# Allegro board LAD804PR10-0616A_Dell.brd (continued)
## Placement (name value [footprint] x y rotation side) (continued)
RC954  10K_0402_5%  [R_0402]  133.93 47.01 0 top
RC967  0_0402_5%  [R_0402]  185.81 24.72 0 bottom
RC1672  0_0603_5%  [R_0603]  122.89 15 180 bottom
RC1675  0_0603_1%  [R0603_0OHM]  122.89 16.27 180 bottom
RD15  0_0402_5%  [R_0402]  175.35 41.51 270 bottom
RD23  1K_0402_1%  [R_0402]  62.45 58.44 180 top
RD24  1K_0402_1%  [R_0402]  61.54 44.91 0 top
RD25  0_0402_5%  [R0402_0OHM]  72.3 50.37 180 top
RD26  1K_0402_1%  [R_0402]  62.45 39.9 180 top
RD27  1K_0402_1%  [R_0402]  44.52 58.95 0 top
RD28  0_0402_5%  [R0402_0OHM]  52.41 51.38 90 top
RD29  0_0402_5%  [R0402_0OHM]  44.52 43.71 0 top
RD32  1K_0402_1%  [R_0402]  44.53 45.66 90 top
RD33  1K_0402_1%  [R_0402]  41.85 41.67 0 top
RE4  0_0805_5%  [R_0805]  176.02 31.85 0 top
RE5  0_0805_5%  [R0805_0OHM]  178.07 23.98 270 top
RE13  0_0805_5%  [R_0805]  176.02 33.63 0 top
RE14  0_0402_5%  [R_0402]  174.39 41.62 270 bottom
RE16  33_0402_5%  [R_0402]  183.97 32.85 0 bottom
RE19  1K_0402_1%  [R_0402]  187.17 30.24 180 bottom
RE20  100K_0402_1%  [R_0402]  166.9 20.54 270 bottom
RE21  10K_0402_5%  [R_0402]  186.72 25.67 180 bottom
RE22  270K_0402_1%  [R_0402]  165.88 19.63 90 bottom
RE23  100K_0402_1%  [R_0402]  164.1 40.71 90 bottom
RE24  0_0402_1%  [R_0402]  165.12 41.62 270 bottom
RE31  0_0402_5%  [R0402_0OHM]  162.88 27.96 0 bottom
RE32  0_0402_5%  [R0402_0OHM]  162.88 28.97 0 bottom
RE33  0_0402_5%  [R0402_0OHM]  162.88 29.99 0 bottom
RE34  0_0402_5%  [R0402_0OHM]  162.88 31.01 0 bottom
RE37  0_0402_5%  [R0402_0OHM]  184.88 34.82 180 bottom
RE38  0_0402_5%  [R0402_0OHM]  184.88 31.26 180 bottom
RE39  0_0402_5%  [R0402_0OHM]  171.02 41.61 270 bottom
RE40  0_0402_5%  [R_0402]  184.88 30.24 180 bottom
RE41  0_0402_5%  [R_0402]  184.88 25.67 180 bottom
RE42  0_0402_5%  [R0402_0OHM]  170.13 40.7 90 bottom
RE43  0_0402_5%  [R_0402]  176.37 40.59 90 bottom
RE44  0_0402_5%  [R_0402]  169.18 41.62 270 bottom
RE46  4.7K_0402_5%  [R_0402]  179.66 40.65 90 bottom
RE48  4.7K_0402_5%  [R_0402]  167.15 40.71 90 bottom
RE49  100K_0402_5%  [R_0402]  160.85 95.78 0 top
RE50  0_0402_5%  [R0402_0OHM]  177.88 38.96 270 top
RE51  0_0402_5%  [R0402_0OHM]  162.88 26.94 0 bottom
RE58  100K_0402_5%  [R_0402]  114.52 9.67 180 top
RE59  0_0805_5%  [R_0805]  120.19 13.67 180 bottom
RE60  240_0402_1%  [R_0402]  63.66 9.4 0 top
RE61  10K_0402_5%  [R_0402]  184.88 29.23 180 bottom
RE62  47K_0402_5%  [R_0402]  177.57 19.63 90 bottom
RE63  47K_0402_5%  [R_0402]  176.55 19.63 90 bottom
RE66  10K_0402_5%  [R_0402]  184.88 28.21 180 bottom
RE68  10K_0402_5%  [R_0402]  117.37 8.6 270 top
RE69  0_0402_5%  [R_0402]  176.87 38.96 270 top
RE70  10K_0402_5%  [R_0402]  162.88 34.56 0 bottom
RE75  10K_0402_5%  [R_0402]  174.77 35.12 90 top
RE338  0_0402_5%  [R0402_0OHM]  94.51 4.64 90 top
RE504  10K_0402_5%  [R_0402]  163.8 32.02 180 bottom
RE505  10K_0402_5%  [R_0402]  145.82 14.04 90 bottom
RF1  10K_0402_5%  [R_0402]  182.4 54.76 224.6 top
RF2  10K_0402_5%  [R_0402]  182.85 47.96 179.9 bottom
RF3  10K_0402_5%  [R_0402]  182.85 47.07 180 bottom
RH21  33_0402_5%  [R_0402]  94.95 74.77 270 top
RH22  10K_0402_5%  [R_0402]  94.65 76.85 180 top
RH23  10K_0402_5%  [R_0402]  94.65 77.74 180 top
RH24  10K_0402_5%  [R_0402]  94 79.79 270 top
RH25  33_0402_5%  [R_0402]  84.3 78.5 180 top
RI1  0_0402_5%  [R_0402-NPM]  20.04 85.72 180 top
RI2  0_0402_5%  [R_0402-NPM]  20.04 84.7 180 top
RI3  150_0402_5%  [R_0402]  17.55 85.67 270 top
RI4  0_0402_5%  [R_0402-NPM]  18.89 88.35 180 top
RI5  0_0402_5%  [R_0402-NPM]  18.89 87.33 180 top
RI6  150_0402_5%  [R_0402]  16.53 88.23 270 top
RI7  0_0402_5%  [R_0402-NPM]  18.96 82.72 180 top
RI8  0_0402_5%  [R_0402-NPM]  18.96 81.7 180 top
RI9  150_0402_5%  [R_0402]  16.53 82.72 270 top
RI10  0_0402_5%  [R_0402-NPM]  19.91 79.01 180 top
RI11  0_0402_5%  [R_0402-NPM]  19.91 80.03 180 top
RI12  150_0402_5%  [R_0402]  17.55 79.06 90 top
RI16  20K_0402_5%  [R_0402]  31.72 92.47 180 top
RI17  100K_0402_5%  [R_0402]  30.8 93.49 0 top
RI18  150K_0402_5%  [R_0402]  30.8 90.44 0 top
RI19  10K_0402_5%  [R_0402]  23.72 97.05 180 top
RI20  100K_0402_5%  [R_0402]  30.8 95.01 0 top
RL1  10K_0402_5%  [R_0402]  38.84 121.23 180 bottom
RL2  2.49K_0402_1%~D  [R_0402]  37.88 116.16 180 bottom
RL3  1K_0402_5%  [R_0402]  34.78 122.65 270 bottom
RL4  15K_0402_1%  [R_0402]  35.8 121.74 90 bottom
RL5  0_0603_1%  [R0603_0OHM]  39.83 113.3 180 bottom
RL6  100K_0402_5%  [R_0402]  22.17 121.94 0 bottom
RL7  10K_0402_5%  [R_0402]  22.17 120.92 0 bottom
RL8  0_0402_5%  [R_0402]  33.33 122.67 270 bottom
RL9  0_0402_5%  [R0402_0OHM]  32.31 121.75 90 bottom
RL10  10K_0402_5%  [R_0402]  36.82 122.65 270 bottom
RL11  10K_0402_5%  [R_0402]  29.18 117.62 180 bottom
RL12  10K_0402_5%  [R_0402]  23.08 122.95 180 bottom
RL14  75_0603_5%  [R_0603]  18.88 112.03 0 top
RL15  75_0603_5%  [R_0603]  18.88 108.48 0 top
RM7  0_1206_5%  [R_1206]  47.01 103.59 90 top
RP1  100K_0402_5%  [R_0402]  221.71 45.99 180 bottom
RP2  10K_0402_5%  [R_0402]  221.71 36.85 180 bottom
RP3  100K_0402_5%  [R_0402]  221.71 37.86 180 bottom
RP20  2.2K_0804_8P4R_5%  [RP_0804_8P4R]  105.31 24.77 180 bottom
RPC13  33_0804_8P4R_5%  [RP_0804_8P4R]  99.51 20.04 0 bottom
RPC14  1K_0804_8P4R_5%  [RP_0804_8P4R]  103.96 21.54 180 bottom
RPC25  1K_0804_8P4R_5%  [RP_0804_8P4R]  109.99 76.66 90 bottom
RPC30  1K_0804_8P4R_5%  [RP_0804_8P4R]  113.57 70.76 270 bottom
RPC36  10K_8P4R_5%  [RP_0804_8P4R]  140.8 41.18 180 top
RPC45  100K_0804_8P4R_5%  [RP_0804_8P4R]  114.31 88.22 270 top
RPC64  2.2K_0804_8P4R_5%  [RP_0804_8P4R]  100.67 38.49 180 bottom
RPE1  2.2K_0804_8P4R_5%  [RP_0804_8P4R]  166.97 28.99 180 top
RPH1  1K_0804_8P4R_5%  [RP_0804_8P4R]  83.91 70.64 180 top
RPH2  1K_0804_8P4R_5%  [RP_0804_8P4R]  83.91 79.79 180 top
RPI1  499_0804_8P4R_1%  [RP_0804_8P4R]  16.23 86.92 180 bottom
RPI2  499_0804_8P4R_1%  [RP_0804_8P4R]  16.23 80.74 180 bottom
RPI3  2.2K_0804_8P4R_5%  [RP_0804_8P4R]  22.56 95.64 0 top
RPV34  10K_8P4R_5%  [RP_0804_8P4R]  117.36 93.93 90 bottom
RS8  0_0402_5%  [R_0402]  194.38 18.56 0 bottom
RS18  0_0402_5%  [R_0402]  191.23 23.13 180 bottom
RS19  0_0402_5%  [R_0402]  200.63 28.72 180 bottom
RS20  0_0402_5%  [R_0402]  190.32 25.16 0 bottom
RS21  0_0402_5%  [R_0402]  199.71 26.69 0 bottom
RS22  0_0402_5%  [R_0402]  190.32 26.18 0 bottom
RS23  0_0402_5%  [R_0402]  191.23 27.2 180 bottom
RS24  2K_0402_5%  [R_0402]  199.71 25.67 0 bottom
RS25  0_0402_5%  [R_0402]  200.63 23.64 180 bottom
RS26  0_0402_5%  [R_0402]  190.32 29.23 0 bottom
RS27  0_0402_5%  [R_0402]  200.63 24.66 180 bottom
RS28  0_0402_5%  [R_0402]  200.63 27.7 180 bottom
RS29  0_0402_5%  [R_0402]  190.32 24.15 0 bottom
RS30  0_0402_5%  [R_0402]  190.32 28.21 0 bottom
RS31  5.1K_0402_1%  [R_0402]  191.23 30.24 180 bottom
RS33  4.7K_0402_5%  [R_0402]  199.71 29.74 0 bottom
RS34  4.7K_0402_5%  [R_0402]  191.23 21.1 180 bottom
RS35  4.7K_0402_5%  [R_0402]  199.71 30.75 0 bottom
RS36  4.7K_0402_5%  [R_0402]  191.23 22.12 180 bottom
RS37  0_0402_5%  [R_0402]  196.25 24.66 180 top
RS38  0_0402_5%  [R_0402]  196.87 25.98 90 top
RS41  0_0402_5%  [R_0402]  193.95 30.96 270 top
RS42  0_0402_5%  [R_0402]  194.86 30.96 270 top
RS43  0_0402_5%  [R_0402]  197.12 30.96 270 top
RS44  0_0402_5%  [R_0402]  196.21 30.96 270 top
RU1  0_0402_5%  [R_0402-NPM]  23.34 57.68 180 top
RU2  0_0402_5%  [R_0402-NPM]  23.34 58.69 180 top
RU3  0_0402_5%  [R_0402-NPM]  23.34 59.71 180 top
RU4  0_0402_5%  [R_0402-NPM]  23.34 60.72 180 top
RU5  0_0402_5%  [R_0402-NPM]  25.32 54.63 180 top
RU6  0_0402_5%  [R_0402-NPM]  25.32 55.64 180 top
RU7  0_0402_5%  [R_0402-NPM]  23.34 38.37 180 top
RU8  0_0402_5%  [R_0402-NPM]  23.34 39.39 180 top
RU9  0_0402_5%  [R_0402-NPM]  23.34 40.4 180 top
RU10  0_0402_5%  [R_0402-NPM]  23.34 41.42 180 top
RU11  0_0402_5%  [R_0402-NPM]  23.34 35.07 180 top
RU12  0_0402_5%  [R_0402-NPM]  23.34 36.09 180 top
RU13  0_0402_5%  [R_0402-NPM]  159.33 15 0 bottom
RU14  0_0402_5%  [R_0402-NPM]  159.33 16.02 0 bottom
RU15  300_0402_5%  [R_0402]  26.5 55.59 90 top
RU16  300_0402_5%  [R_0402]  24.91 36.14 90 top
RU17  0_0402_5%  [R_0402-NPM]  183.34 20.54 270 bottom
RU18  0_0402_5%  [R_0402-NPM]  182.33 20.54 270 bottom
RV1  1.69K_0402_1%  [R_0402]  110.26 118.05 90 top
RV2  1K_0402_1%  [R_0402]  113.73 107.34 0 top
RV3  1K_0402_1%  [R_0402]  109.33 118.02 90 top
RV4  100K_0402_5%  [R_0402]  98.82 120.37 270 bottom
RV5  45.3K_0402_1%  [R_0402]  102.85 82.63 90 top
RV6  45.3K_0402_1%  [R_0402]  106.24 89.43 0 top
RV8  8.45K_0402_1%  [R_0402]  104.84 113.17 90 top
RV9  2K_0402_1%  [R_0402]  105.74 114.07 270 top
RV11  8.45K_0402_1%  [R_0402]  103.05 115.51 270 top
RV12  2K_0402_1%  [R_0402]  103.94 114.61 90 top
RV13  4.75K_0402_1%  [R_0402]  103.05 112.82 90 top
RV15  8.45K_0402_1%  [R_0402]  102.24 118.47 0 top
RV16  4.75K_0402_1%  [R_0402]  103.49 117.57 180 top
RV17  1K_0402_1%  [R_0402]  117.62 88.71 90 top
RV20  1M_0402_5%  [R_0402]  98.86 122.92 270 bottom
RV21  10K_0402_5%  [R_0402]  113.1 97.37 90 bottom
RV27  0_0603_1%  [R0603_0OHM]  102.2 108.23 180 top
RV28  8.45K_0402_1%  [R_0402]  99.7 112.98 0 top
RV29  10K_0402_5%  [R_0402]  107.28 118.7 270 top
RV30  0_0603_1%  [R0603_0OHM]  103.1 106.98 180 top
RV31  0_0805_5%  [R0805_0OHM]  108.83 122.38 0 top
RV32  40.2_0402_1%  [R_0402]  120.52 125.31 90 bottom
RV33  40.2_0402_1%  [R_0402]  119.64 125.32 180 bottom
RV34  100_0402_1%  [R_0402]  117.83 126.21 180 bottom
RV35  100_0402_1%  [R_0402]  120.59 127.1 180 bottom
RV36  49.9_0402_1%  [R_0402]  126.96 89.38 270 top
RV37  10_0402_1%  [R_0402]  126 89.38 270 top
RV38  5.1K_0402_1%  [R_0402]  119.15 101.95 270 top
RV39  120_0402_1%  [R_0402]  115.97 126.46 270 bottom
RV40  51.1_0402_1%  [R_0402]  118.6 86.7 90 top
RV41  51.1_0402_1%  [R_0402]  115.39 100.6 0 top
RV48  2.37K_0402_1%  [R_0402]  154.31 99.86 180 top
RV49  5.49K_0402_1%  [R_0402]  153.4 101.64 0 top
RV50  2.37K_0402_1%  [R_0402]  145.35 94.64 90 bottom
RV51  5.49K_0402_1%  [R_0402]  143.57 95.55 270 bottom
RV52  2.37K_0402_1%  [R_0402]  153.22 125.15 270 top
RV53  5.49K_0402_1%  [R_0402]  153.14 122.4 0 top
RV54  2.37K_0402_1%  [R_0402]  143.8 128.88 270 bottom
RV55  5.49K_0402_1%  [R_0402]  142.78 127.96 90 bottom
RV59  10K_0402_5%  [R_0402]  108.34 118.93 270 top
RV71  0_0402_5%  [R_0402]  78.96 92.54 180 top
RV72  0_0402_5%  [R_0402]  76.68 92.54 180 top
RV73  10K_0402_5%  [R_0402]  87.27 94.49 90 top
RV74  10K_0402_5%  [R_0402]  85.24 95.41 270 top
RV75  10K_0402_5%  [R_0402]  86.25 92.52 90 top
RV76  0_0402_5%  [R_0402]  86.25 94.68 90 top
RV79  60.4_0402_1%  [R_0402]  143.8 128.87 270 top
RV80  60.4_0402_1%  [R_0402]  144.69 128.87 270 top
RV81  4.7K_0402_5%  [R_0402]  110.83 98.27 270 bottom
RV82  4.7K_0402_5%  [R_0402]  111.78 98.27 270 bottom
RV83  16.2K_0402_1%  [R_0402]  108.54 98.27 270 bottom
RV84  10K_0402_5%  [R_0402]  97.38 106.95 180 bottom
RV85  60.4_0402_1%  [R_0402]  144.65 94.64 90 top
RV86  60.4_0402_1%  [R_0402]  143.76 94.64 90 top
RV87  10K_0402_5%  [R_0402]  97.38 107.97 180 bottom
RV88  10K_0402_5%  [R_0402]  97.3 109.82 270 bottom
RV89  10K_0402_5%  [R_0402]  99.66 106.06 180 bottom
RV90  1K_0402_1%  [R_0402]  113.59 104.2 270 top
RV91  10K_0402_5%  [R_0402]  113.58 102.4 0 top
RV92  10K_0402_5%  [R_0402]  85.24 93.44 270 top
RV93  0_0402_5%  [R_0402]  75.76 93.49 0 top
RV94  0_0402_5%  [R_0402]  75.76 94.38 0 top
RV100  33_0402_5%  [R_0402]  78.96 94.38 180 top
RV101  33_0402_5%  [R_0402]  78.96 93.49 180 top
RV102  10K_0402_5%  [R_0402]  78.96 95.27 180 top
RV103  0_0402_5%  [R_0402]  87.27 92.52 90 top
RV117  1K_0402_1%  [R_0402]  144.25 111.35 0 bottom
RV119  1K_0402_1%  [R_0402]  153.4 102.53 0 bottom
RV121  121_0402_1%  [R_0402]  142.68 95.55 270 bottom
RV131  1K_0402_1%  [R_0402]  144.25 112.31 0 bottom
RV132  121_0402_1%  [R_0402]  145.59 127.98 90 bottom
RV133  1K_0402_1%  [R_0402]  153.11 121.33 0 bottom
RV150  0_0402_5%  [R_0402]  120.76 92.37 0 bottom
RV151  10K_0402_5%  [R_0402]  116.43 97.46 90 bottom
RV152  10K_0402_5%  [R_0402]  114.99 98.36 270 bottom
RV153  0_0402_5%  [R_0402]  114.04 97.37 90 bottom
RV154  5.1K_0402_1%  [R_0402]  116.67 89.63 270 top
RV155  0_0402_5%  [R_0402]  99.66 108.98 180 bottom
RV156  0_0402_5%  [R_0402]  99.66 107.97 180 bottom
RV157  0_0402_5%  [R_0402]  99.64 106.98 180 bottom
RV158  0_0402_5%  [R_0402]  105.47 117.95 270 top
RV159  0_0402_5%  [R_0402]  106.37 117.95 270 top
RV160  10_0402_5%  [R_0402]  105.41 118.85 180 top
RV161  10_0402_5%  [R_0402]  106.48 120.3 90 top
RV162  4.7K_0402_5%  [R_0402]  98.01 117.39 0 bottom
RV163  4.7K_0402_5%  [R_0402]  98.92 118.29 180 bottom
RV164  0_0402_5%  [R0402_0OHM]  122.61 92.42 90 bottom
RV165  0_0402_5%  [R_0402]  123.37 91.43 270 bottom
RV260  4.7K_0402_5%  [R_0402]  118.69 93.49 0 bottom
RV364  0_0603_1%  [R0603_0OHM]  110.38 125.05 0 top
RV367  0_0603_5%  [R_0603]  108.13 107.55 90 top
RV368  10K_0402_5%  [R_0402]  114.66 99.29 0 bottom
RV369  10K_0402_5%  [R_0402]  118.51 96.04 270 bottom
RW4  0_0402_5%  [R_0402]  54.63 109.54 90 top
RW6  0_0402_5%  [R_0402]  52.09 110.46 270 top
RW7  0_0402_5%  [R_0402]  53.11 110.46 270 top
RW8  100K_0402_5%  [R_0402]  51.07 109.54 90 top
RW9  0_0402_5%  [R_0402]  58.95 112.24 270 top
RW10  0_0402_5%  [R_0402]  59.96 112.24 270 top
RW11  0_0402_5%  [R0402_0OHM]  55.65 109.54 90 top
RW12  10K_0402_5%~D  [R_0402]  54.63 105.22 90 top
RW13  10K_0402_5%~D  [R_0402]  58.57 104.59 90 top
RX2  100_0402_5%  [R_0402]  220.8 44.98 0 bottom
RX7  0_0402_5%  [R0402_0OHM]  222.09 47.9 180 top
RX8  0_0402_5%  [R_0402]  222.09 48.79 180 top
RX9  10K_0402_5%  [R_0402]  227.54 43.38 180 top
RX25  33_0402_5%  [R_0402]  221.97 28.72 180 bottom
SW1  TST71-N-220-T170-S017_2P  [SW_TST71-N-220-T170-S017_2P]  164.94 86.12 180 top
SW2  TST71-N-220-T170-S017_2P  [SW_TST71-N-220-T170-S017_2P]  164.94 86.12 180 bottom
T34  -  [TPC12]  109.06 60.46 0 top
T35  -  [TPC12]  110.15 61.28 0 top
T36  -  [TPC12]  112.67 59.64 0 top
T38  -  [TPC12]  108.39 56.81 0 top
T39  -  [TPC12]  108.35 59.01 0 top
T41  -  [TPC12]  107.97 61.27 0 top
T42  -  [TPC12]  120.48 57.93 0 top
T43  -  [TPC12]  121.88 57.99 0 top
T44  -  [TPC12]  107.92 62.81 0 top
T45  -  [TPC12]  100.99 54.44 180 bottom
T46  -  [TPC12]  109.27 62.91 0 top
T48  -  [TPC12]  119.15 39.31 180 bottom
T49  -  [TPC12]  119.53 36.21 180 bottom
T50  -  [TPC12]  118.77 37.25 180 bottom
T51  -  [TPC12]  118.18 38.4 180 bottom
T52  -  [TPC12]  118.51 31.64 180 bottom
T73  -  [TPC12]  117.98 39.85 180 bottom
T74  -  [TPC12]  194.33 45.99 180 bottom
T75  -  [TPC12]  198.39 45.99 180 bottom
T76  -  [TPC12]  130.45 53.17 180 bottom
T77  -  [TPC12]  106.38 64.92 0 top
T94  PAD  [TPC12]  36.47 119.08 180 bottom
T95  PAD  [TPC12]  38.37 122.26 180 bottom
T201  -  [TPC12]  114.57 106.32 0 top
T202  -  [TPC12]  115.97 106.19 0 top
T203  -  [TPC12]  99.02 102.57 180 bottom
T204  -  [TPC12]  109.87 106.89 0 top
T205  -  [TPC12]  105.24 98.57 180 bottom
T206  -  [TPC12]  99.59 105.11 180 bottom
T207  -  [TPC12]  107.34 106.06 0 top
T208  -  [TPC12]  106.13 97.63 180 bottom
T209  -  [TPC12]  104.19 97.8 180 bottom
T210  -  [TPC12]  106.51 99.01 180 bottom
T211  -  [TPC12]  108.8 105.56 0 top
T212  -  [TPC12]  107.72 104.35 0 top
T213  -  [TPC12]  109.56 97.36 180 bottom
T214  -  [TPC12]  107.78 99.33 180 bottom
T215  -  [TPC12]  107.46 97.87 180 bottom
T216  -  [TPC12]  110.95 99.4 180 bottom
T217  -  [TPC12]  110.07 99.4 180 bottom
T218  -  [TPC12]  108.07 111.74 0 top
T221  -  [TPC12]  109.05 99.4 180 bottom
T222  -  [TPC12]  110.07 98.76 180 bottom
T223  -  [TPC12]  113.56 99.27 180 bottom
T224  -  [TPC12]  112.26 99.23 180 bottom
T4935  -  [TPC12]  99.08 103.9 180 bottom
TL1  350UH_NS14-1-LF  [BOTH_NS14-1-LF_12P]  28 114.65 270 bottom
U1  -  [SY6288C20AAC_SOT23-5]  227.13 46.12 0 top
U2  -  [LM393DR_SO8]  127.82 6.5 270 bottom
U4  AO4354_SO8  [AO4430L_SO8]  139.17 17.67 90 bottom
U15  EM5209VF DFN 14P DUAL LOAD SW  [TPS22966DPUR_SON14_2X3-S]  102.93 95.98 270 bottom
U74  -  [SY6288C20AAC_SOT23-5]  110.7 92.04 180 bottom
U2301  EM5209VF DFN 14P DUAL LOAD SW  [TPS22966DPUR_SON14_2X3-S]  161.63 11.2 0 bottom
U2302  EM5209VF DFN 14P DUAL LOAD SW  [TPS22966DPUR_SON14_2X3-S]  157.76 23.06 270 bottom
U2407  F75303M_MSOP10  [EMC1403-2-AIZL-TR_MSOP10]  72.8 13.97 270 top
UA1  ALC3246-CG_MQFN48_6X6  [ALC3246-CG_MQFN48_6X6-S]  30.16 30.25 270 top
UC1  2D3201AJN23AC_BGA769~D  [2D3201AJN23AC_BGA_769P]  125.96 64.81 180 bottom
UC4  MC74VHC1G08DFT2G SC70 5P  [NC7SZ08P5X_NL_SC70-5]  108.99 26.94 90 bottom
UC5  -  [W25Q128FVSIQ_SO8]  112.22 17.67 90 bottom
UC61  NL17SZ07DFT2G_SC70-5  [SN74LVC1G07DCKR_SC70-5]  138.3 52.96 90 top
UC62  NL17SZ07DFT2G_SC70-5  [SN74LVC1G07DCKR_SC70-5]  119.77 82.97 0 top
UC63  NL17SZ07DFT2G_SC70-5  [SN74LVC1G07DCKR_SC70-5]  125.61 91.06 0 bottom
UC64  NL17SZ07DFT2G_SC70-5  [SN74LVC1G07DCKR_SC70-5]  112.34 83.1 0 top
UC65  NL17SZ07DFT2G_SC70-5  [SN74LVC1G07DCKR_SC70-5]  118.27 84.71 180 top
UC101  AP2138N-1.5TRG1_SOT23-3  [AP2138N-1P5TRG1_SOT23-3]  39.11 6.88 90 bottom
UE1  -  [KB9022QD_LQFP128_14X14]  181.65 36.82 180 bottom
UI5  -  [SY6288D20AAC_SOT23-5]  21.42 64.86 0 top
UL1  RTL8106E-CG_QFN32_4X4  [RTL8106E-CG_QFN32_4X4-S]  34.69 115.8 180 bottom
UL3  AP22802AW5-7 SOT25 5P  [SY6288C20AAC_SOT23-5]  26.37 120.48 180 bottom
US2  SN75LVCP601RTJR_QFN20_4X4  [PS8520BTQFN20GTR2_TQFN20_4X4-S]  194.35 28.08 0 bottom
UU3  -  [SY6288D20AAC_SOT23-5]  172.29 18.17 180 top
UV1  2160856030-A0_FCBGA631  [216-0842024-A11-MAR_FCBGA_631P]  123.7 101.5 90 bottom
UV2  MC74VHC1G08DFT2G_SC70-5  [SN74AHC1G08DCKR_SC70-5]  94.28 118.79 90 bottom
UV3  MC74VHC1G08DFT2G_SC70-5  [SN74AHC1G08DCKR_SC70-5]  122.18 89.13 180 bottom
UV4  S IC SN74AVC2T45DCTR_SM8  [SN74LVC2T45DCTR_SM8]  84.07 93.11 90 top
UV13  H5GC4H24AJR-R0C_BGA170  [H5GC4H24AJR-R0C_BGA_170P]  150.67 115.21 90 bottom
UV15  H5GC4H24AJR-R0C_BGA170  [H5GC4H24AJR-R0C_BGA_170P]  137.87 108.61 270 bottom
YC2  48MHZ_8PF_X3S048000D81H-W  [Y_X3S048000D81H-W_4P]  133.71 63.86 270 bottom
YC3  32.768KHZ_12.5PF_CM31532768DZFT  [Y_CM31532768DZFT_2P]  136.42 36.87 90 bottom
YL1  25MHZ_10PF_7V25000014  [Y_7V25000014_4P]  40.49 119.74 270 bottom
YV1  27MHZ_10PF_7V27000050  [Y_7V27000011_4P]  96.6 123.82 270 bottom

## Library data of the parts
C2 C3 C6 C16 C19 C22 C24 C26 C27 C35-C49 C343 C344 C349 C551 C553 C622 C625 C636 C796 C797 C983 C987 C2307 C2324 C2498 C2500 C2502 C2504 C2505 C4311-C4314 C4321 C4322 C5216 C5219 CA2 CA4 CA6 CA8 CA10 CA14 CA16 CA17 CA27-CA31 CA34-CA37 CA39-CA42 CC14-CC16 CC23 CC29-CC32 CC50-CC53 CC99 CC166 CC203 CC224-CC227 CC245 CC615 CC635 CC682 CC686 CC912 CC923 CC999 CC1000 CC1005-CC1007 CC1052 CC1067 CC1078 CC1079 CC1081 CC1082 CC1084 CC1086-CC1093 CC1102 CC1104-CC1107 CC1110-CC1117 CC1119-CC1123 CC1125-CC1129 CC1139-CC1146 CC1148 CC1150 CC1151 CD193 CD200-CD208 CD211-CD228 CD231 CD234 CD237 CD245-CD253 CD256 CD259 CD262 CD265-CD268 CE3 CE4 CE10 CE13 CE14 CE17 CE20 CE21 CE23-CE25 CE33 CE39-CE43 CE47 CH1 CH2 CI1-CI18 CL1 CL2 CL5 CL6 CL8-CL12 CL14 CS5 CS6 CS8-CS11 CS13-CS15 CS27 CS30-CS42 CU1-CU4 CU7-CU10 CU14 CU15 CU19 CU21-CU23 CV1-CV8 CV11 CV15 CV17 CV18 CV20 CV21 CV26 CV28 CV29 CV33-CV35 CV39-CV42 CV46-CV53 CV56-CV60 CV62-CV66 CV71-CV80 CV82 CV85-CV87 CV89 CV90 CV92-CV121 CV124-CV127 CV153 CV155 CV157 CV158 CV160-CV162 CV164-CV166 CV169 CV170 CV173-CV181 CV183-CV186 CV198 CV210 CV211 CV213 CV216 CV219 CV221 CV227 CV230 CV233 CV235 CV242 CV243 CV247 CV248 CV304-CV309 CV312 CV313 CV333-CV336 CV341-CV344 CV390 CV391 CV394 CV395 CVT90 CW12-CW17 CX1 EC2901 EC2902 PC1-PC4 PC7 PC8 PC14 PC16 PC100 PC102 PC103 PC113-PC116 PC127 PC128 PC130-PC133 PC200-PC203 PC207 PC208 PC210 PC213 PC214 PC230 PC231 PC301-PC303 PC305 PC309 PC320 PC321 PC401 PC403 PC404 PC602-PC604 PC705 PC708 PC711 PC721 PC742 PC744 PC747-PC749 PC751-PC753 PC765 PC768 PC769 PC777 PC779-PC781 PC790 PC803 PC805 PC901 PC903 PC905 PC1004 PC1006-PC1011 PC1015 PC1018 PC1037 PC1038 PC1056-PC1062 PC1064 PC1066 PC1068 PC1069 PC1071-PC1076 PC1101 PC1106-PC1108 PC1115-PC1120 PC1122-PC1125 PC1127 PC1128 PC1130 PC1131 PC1140-PC1143 PC1401 PC1402 PC1404-PC1407 PC1409 PC1420 PC1421 = C_0402
C4 C5 C17 C18 C34 C431 C432 C620 C621 C623 C939 C940 C2305 C2306 C2308 C2309 C2316 C2318 C2322 C2323 C2618-C2622 CA1 CA3 CA5 CA11-CA13 CA15 CA20-CA26 CA32 CA33 CC119 CC120 CC934 CC935 CC949-CC951 CC1008-CC1011 CC1015 CC1016 CC1053-CC1055 CC1057-CC1066 CC1068 CC1080 CC1083 CC1085 CC1095-CC1098 CC1100 CC1101 CC1108 CC1109 CC1118 CC1124 CC1137 CC1147 CD194-CD199 CD209 CD210 CD232 CD233 CD239-CD244 CD254 CD255 CD260 CD261 CE56 CL7 CU13 CU18 CV19 CV27 CV30 CV38 CV43-CV45 CV54 CV55 CV61 CV67-CV70 CV81 CV84 CV88 CV91 CV122 CV123 CV182 CV225 CV238 CW10 CW11 PC111 PC112 PC119 PC125 PC126 PC204 PC209 PC215-PC220 PC306 PC601 PC605-PC607 PC750 PC757 PC767 PC802 PC804 PC911-PC917 PC931 PC932 PC1012-PC1014 PC1053-PC1055 PC1063 PC1065 PC1109-PC1111 PC1121 PC1126 PC1129 PC1408 PC1411-PC1414 = C_0603
CD229 CD230 CD258 = C_D3
CF4 CS7 CS12 CU6 CU11 CU12 CU16 CU17 CU20 PC104-PC110 PC117 PC118 PC120-PC124 PC205 PC206 PC211 PC212 PC304 PC308 PC402 PC405 PC760-PC764 PC766 PC775 PC776 PC778 PC801 PC902 PC904 PC1002 PC1003 PC1039 PC1067 PC1070 PC1103-PC1105 PC1112-PC1114 PC1403 = C_0805
CL13 = C_1206
CLIP1 CLIP2 = EMIST_SQ-55G_1P
CLRP1 = SHORTPADS: User Part Number: PART#
D4 DX1 = RB751V-40_SOD323-2
DA1 DA2 = AZ5125-02SPR7G_SOT23-3
DA3 = BAT54C-7-F_SOT23-3
DA4 = L03ESDL5V0CC3-2_SOT23-3
DA5 = AZ5123-02SPR7G_SOT23-3
DC3 = RB751V-40TE17_SOD323-2
DC3803 = BAS40C_SOT23-3
DF1 PD102 = SDMK0340L-7-F_SOD323-2
DH1 DH2 = DB2J31400L_SOD323-2
DU1 EU2602 EU2604 = AZC199-02SPR7G_SOT23-3
DX2 = PESD5V0U2BT_SOT23-3
ED2901 = AZ5725-01F_DFN2
EU2601 EU2603 = L05ESDL5V0NA-4_SLP2510P8-10-9
EU3501 = TVWDF1004AD0_DFN9
F1 F2 = F_SMD1812P110TF-24
F3 = F_MF-NSMF050-2
FD1-FD4 = FIDUCIAL_C40M80
FI1 = F_1206L150PR
H1-H5 = H_3P0-G
H6 = H_5P6N
H7 = H_3P0N
H8-H10 = H_3P5-G
H11 = H_3P2
H12 = H_3P2X2P6
H13 = H_6P0
HCPU1 HCPU4 = H_3P7X4P3
HCPU2 = H_3P7
HCPU3 = H_3P9
J10 J510 JP7 JP13 PJP203 PJP401 PJP402 PJP601 PJP602 PJP801-PJP803 PJP901 PJP902 = JUMP_43X79
J11 J509 J511 PJP102 PJP103 PJP200 PJP201 PJP301 PJP302 PJP1402 = JUMP_43X118
JDIMM1 = DEREN_40-42271-26001RHF_260P-T
JDIMM2 = DEREN_40-42261-26001RHF_260P-T
JEDP1 = ACES_51540-04001-P01_40P
JFAN1 JSPK1 = JXT_WB247H-004S10M_4P
JH1 = ACES_91960-0084L_8P-T
JHDD1 = ACES_51625-01201-001_12P
JHDMI1 = CONCR_099AKAC19NBLCNF_19P
JHDT1 = SAMTE_ASP-136446-07-B_20P-T
JHP1 = YUQIU_PJ753-F07J1BE-B_7P-T
JIOB1 = ACES_51524-0160N-001_16P
JKB1 = STARC_132C30-100020-A2-R_30P
JKBBL1 = ACES_51575-00401-001_4P-T
JLAN1 = SANTA_130460-N_8P-T
JLED1 = ACES_51524-0040N-001_4P
JODD1 = ACES_50673-0120N-001_12P-T
JP2 JP3 JP12 JP14 = JUMP_43X39
JPWR1 = JXT_FP226H-006S1BM_6P
JRTC1 = ACES_50271-0020N-001_2P
JTP1 = JXT_FP202DH-008M10M_8P
JUSB1 JUSB2 = ACON_TARA4-9K1311_9P
JWLAN1 = LCN_DAN05-67406-0100_67P
L3 LU3 LU6-LU8 = INPAQ_MCM1012B900F06BP_4P
LA1 LV6 = MURAT_BLM15BB221SN1D_2P
LA3-LA6 LA8 LA9 LV2-LV4 LV7 LV8 PH1 PH1000-PH1003 PH1101 PH1102 PR2-PR4 PR6-PR16 PR18 PR20 PR24 PR28 PR29 PR31-PR33 PR102 PR103 PR107-PR110 PR113-PR115 PR117 PR118 PR122 PR204 PR205 PR207-PR209 PR211 PR302 PR304 PR306-PR311 PR401-PR403 PR602-PR605 PR727 PR729 PR731 PR732 PR737 PR738 PR740-PR742 PR745 PR749-PR757 PR760 PR762-PR764 PR774 PR777 PR781 PR790 PR791 PR802 PR803 PR901 PR902 PR1000 PR1002-PR1005 PR1007 PR1009 PR1011 PR1013-PR1016 PR1018 PR1021 PR1028 PR1047 PR1051 PR1065-PR1068 PR1070-PR1073 PR1076-PR1081 PR1086 PR1087 PR1101 PR1104-PR1106 PR1110-PR1113 PR1117 PR1119-PR1121 PR1124 PR1128-PR1137 PR1140 PR1401 PR1404 PR1406 PR1407 PR1409-PR1411 R5 R23 R27 R28 R31 R32 R35 R36 R39 R41 R53 R54 R56 R150 R437-R439 R1563 R1674 R2313 R2318 R2448 R2450 R2634-R2636 RA6-RA8 RA10 RA12-RA14 RA16 RA25-RA34 RA41 RA43-RA45 RA49 RA55 RA56 RC1 RC2 RC4-RC13 RC16 RC17 RC21 RC23 RC25-RC31 RC33 RC40-RC46 RC48-RC51 RC54-RC61 RC70 RC75 RC80 RC81 RC90 RC93 RC96 RC106 RC117 RC118 RC154 RC155 RC159 RC346 RC350 RC400 RC401 RC449 RC450 RC541 RC542 RC602 RC617 RC639-RC646 RC654 RC661-RC664 RC666 RC669 RC670 RC673 RC678 RC683 RC690-RC697 RC703 RC706-RC712 RC902-RC907 RC914 RC925-RC929 RC932 RC933 RC938 RC939 RC942-RC944 RC949-RC954 RC967 RD15 RD23 RD24 RD26 RD27 RD32 RD33 RE14 RE16 RE19-RE24 RE40 RE41 RE43 RE44 RE46 RE48 RE49 RE58 RE60-RE63 RE66 RE68-RE70 RE75 RE504 RE505 RF1-RF3 RH21-RH25 RI3 RI6 RI9 RI12 RI16-RI20 RL1-RL4 RL6-RL8 RL10-RL12 RP1-RP3 RS8 RS18-RS31 RS33-RS38 RS41-RS44 RU15 RU16 RV1-RV6 RV8 RV9 RV11-RV13 RV15-RV17 RV20 RV21 RV28 RV29 RV32-RV41 RV48-RV55 RV59 RV71-RV76 RV79-RV94 RV100-RV103 RV117 RV119 RV121 RV131-RV133 RV150-RV163 RV165 RV260 RV368 RV369 RW4 RW6-RW10 RW12 RW13 RX2 RX8 RX9 RX25 = R_0402
LA7 LA10 = MURAT_BLM15PX330SN1D_2P
LC22 = KC_FBMA-L11-201209-121LMA50_2P
LE3 LE4 = KC_FBMA-L11-160808-800LMT_2P
LI1-LI4 = INPAQ_HCM1012GH900BP_4P
LU1 LU2 LU4 LU5 = INPAQ_HCM1012GD670A05P_4P
LX1 = TAI-T_HCB2012KF-221T30_2P
PBATT1 = ACES_50458-01001-P01_10P-T
PC307 PC310 PC954-PC956 PC959 PC960 = C_D2
PC836-PC839 = C_5X4P5
PC1000 PC1001 = C_25CL33LD
PD2-PD4 = TVNST52302AB0_SOT523-3
PD5 PD6 = BAV99W_SC70-3
PD704 = LRB715FT1G_SOT323-3
PJP1-PJP3 PJP105 PJP106 PJP206 PJP303 PJP1001 PJP1101 PJP1401 = JUMP_43X79-NPM
PJP701 = JUMP_43X118-NPM
PJPDC1 = ACES_50458-00601-001_6P-T
PL1 PL3 PL4 PL102 PL103 PL201 PL301 PL1001 PL1101 PL1402 = 5A_Z150_1210_2P
PL2 = MURAT_BLM15AG102SN1D_2P
PL100 PL101 PL200 PL302 PL700 = L_7X7X3_M_2P
PL601 PL704 PL1401 = L_5X5X3_M_2P
PL1002 PL1004 PL1102 PL1103 = L_7X7X4_M
PQ1 PQ2 = 2N7002DW-T-R7_SOT363-6
PQ3 PQ709 PQ712 = L2N7002WT1G_SC70-3
PQ5 = RHU002N06_SOT323-3
PQ6 = FDV301N_NL_SOT23-3
PQ201 = AON7934_DFN3X3A8-10
PQ301 PQ302 PQ1001-PQ1003 PQ1007-PQ1009 PQ1101-PQ1106 = SIR472DP-T1-GE3_POWERPAK8-5
PQ704 PQ708 = SIS412DN-T1-GE3_POWERPAK8-5
PQ710 = LMUN5113T1G_SOT323-3
PQ711 = LTC015EUBFS8TL_UMT3F
PQ717 PQ718 PQ740 = MDU1512RH_POWERDFN56-8-5
PQ720 PQ721 = RUM002N02GT2L_VMT3
PQ801 QW1 = SSM3K7002FU_SC70-3
PR5 PR106 PR112 PR203 PR305 PR606 PR743 PR766 PR1010 PR1074 PR1107 PR1125 PR1408 RM7 = R_1206
PR100 PR111 PR206 PR210 PR771 PR780 PR1008 PR1012 PR1026 PR1082 PR1084 PR1108 PR1114 PR1126 R11 R12 R38 R1671 RC1672 RL14 RL15 RV367 = R_0603
PR116 PR120 PR121 PR201 PR202 PR212 PR301 PR601 PR769 PR770 PR772 PR775 PR776 PR778 PR779 PR801 PR903 PR1006 PR1023 PR1069 PR1075 PR1085 PR1115 PR1116 PR1122 PR1138 PR1139 PR1403 PR1405 R6 R7 R13 R37 RA5 RA11 RA15 RA17-RA21 RA40 RC18 RC22 RC32 RC52 RC53 RC119 RC458 RC665 RD25 RD28 RD29 RE31-RE34 RE37-RE39 RE42 RE50 RE51 RE338 RL9 RV164 RW11 RX7 = R0402_0OHM
PR200 PR303 PR761 PR773 PR1103 PR1123 PR1402 R14 R16 RA4 RA42 RC1675 RL5 RV27 RV30 RV364 = R0603_0OHM
PR703 PR765 = R_1206_4P
PU100 = SY8286BRAC_QFN20_3X3-S
PU102 = SY8286CRAC_QFN20_3X3-S
PU200 = RT8207PGQW_WQFN20_3X3-S
PU300 = TPS51212DSCR_SON10_3X3-S
PU400 PU900 = RT904225GSP_SO8
PU600 = SY8033BDBC_DFN10_3X3-S
PU703 = ISL95520HRZ-T_QFN32_4X4-S
PU800 = APL5336KAI-TRL_SOP8P8
PU1001 PU1100 = ISL62771HRTZ-T_TQFN40_5X5-S
PU1400 = SY8286RAC_QFN20_3X3-S
Q2 Q2516 QC79 QI2 = DMN66D0LDW-7_SOT363-6
Q3 Q7 Q12 Q15 Q83-Q85 Q91 Q6102 QI1 = 2N7002K_SOT23-3
Q5 = 2N7002KW_SOT323-3
Q6 Q8 Q9 Q16 QA1 = LN2306LT1G_SOT23-3
Q135 Q2513-Q2515 = AO3416_SOT23-3
Q2407 Q2408 = MMST3904-7-F_SOT323-3
QC2 = MESS138W-G_SOT323-3
QE4 = 2N7002BKW_SOT323-3
QI3 = MMBT3904_NL_SOT23-3
QV1 = 2N7002KDWH_SOT363-6
R4 RE4 RE13 RE59 = R_0805
R17 R18 RI1 RI2 RI4 RI5 RI7 RI8 RI10 RI11 RU1-RU14 RU17 RU18 = R_0402-NPM
R51 RA1 RA2 RA22 RE5 RV31 = R0805_0OHM
RP20 RPC13 RPC14 RPC25 RPC30 RPC36 RPC45 RPC64 RPE1 RPH1 RPH2 RPI1-RPI3 RPV34 = RP_0804_8P4R
SW1 SW2 = SW_TST71-N-220-T170-S017_2P
T34-T36 T38 T39 T41-T46 T48-T52 T73-T77 T94 T95 T201-T218 T221-T224 T4935 = TPC12
TL1 = BOTH_NS14-1-LF_12P
U1 U74 UL3 = SY6288C20AAC_SOT23-5
U2 = LM393DR_SO8
U4 = AO4430L_SO8
U15 U2301 U2302 = TPS22966DPUR_SON14_2X3-S
U2407 = EMC1403-2-AIZL-TR_MSOP10
UA1 = ALC3246-CG_MQFN48_6X6-S
UC1 = 2D3201AJN23AC_BGA_769P
UC4 = NC7SZ08P5X_NL_SC70-5
UC5 = W25Q128FVSIQ_SO8
UC61-UC65 = SN74LVC1G07DCKR_SC70-5
UC101 = AP2138N-1P5TRG1_SOT23-3
UE1 = KB9022QD_LQFP128_14X14
UI5 UU3 = SY6288D20AAC_SOT23-5
UL1 = RTL8106E-CG_QFN32_4X4-S
US2 = PS8520BTQFN20GTR2_TQFN20_4X4-S
UV1 = 216-0842024-A11-MAR_FCBGA_631P
UV2 UV3 = SN74AHC1G08DCKR_SC70-5
UV4 = SN74LVC2T45DCTR_SM8
UV13 UV15 = H5GC4H24AJR-R0C_BGA_170P
YC2 = Y_X3S048000D81H-W_4P
YC3 = Y_CM31532768DZFT_2P
YL1 = Y_7V25000014_4P
YV1 = Y_7V27000011_4P

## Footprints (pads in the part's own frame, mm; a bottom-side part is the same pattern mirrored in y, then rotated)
2D3201AJN23AC_BGA_769P
  round 0.406 smd: A2(0.6,0) A3(1.35,0) A39(21.25,0) A40(22,0) AA4(2.1,-11.3) AA5(2.9,-11.3) AA7(3.7,-11.3) AA8(4.5,-11.3) AA10(5.3,-11.3) AA11(6.3,-11.3) AA13(7.3,-11.3) AA15(8.3,-11.3) AA17(9.3,-11.3) AA19(10.3,-11.3) AA21(11.3,-11.3) AA23(12.3,-11.3) AA25(13.3,-11.3) AA27(14.3,-11.3) AA29(15.3,-11.3) AA31(16.3,-11.3) AA32(17.3,-11.3) AA34(18.1,-11.3) AA35(18.9,-11.3) AA37(19.7,-11.3) AA38(20.5,-11.3) AC4(2.1,-12.4) AC5(2.9,-12.4) AC7(3.7,-12.4) AC8(4.5,-12.4) AC10(5.3,-12.4) AC11(6.3,-12.3) AC13(7.3,-12.3) AC15(8.3,-12.3) AC17(9.3,-12.3) AC19(10.3,-12.3) AC21(11.3,-12.3) AC23(12.3,-12.3) AC25(13.3,-12.3) AC27(14.3,-12.3) AC29(15.3,-12.3) AC31(16.3,-12.3) AC32(17.3,-12.4) AC34(18.1,-12.4) AC35(18.9,-12.4) AC37(19.7,-12.4) AC38(20.5,-12.4) AE4(2.1,-13.5) AE5(2.9,-13.5) AE7(3.7,-13.5) AE8(4.5,-13.5) AE10(5.3,-13.5) AE11(6.3,-13.3) AE13(7.3,-13.3) AE15(8.3,-13.3) AE17(9.3,-13.3) AE19(10.3,-13.3) AE21(11.3,-13.3) AE23(12.3,-13.3) AE25(13.3,-13.3) AE27(14.3,-13.3) AE29(15.3,-13.3) AE31(16.3,-13.3) AE32(17.3,-13.5) AE34(18.1,-13.5) AE35(18.9,-13.5) AE37(19.7,-13.5) AE38(20.5,-13.5) AG4(2.1,-14.6) AG5(2.9,-14.6) AG7(3.7,-14.6) AG8(4.5,-14.6) AG10(5.3,-14.6) AG11(6.3,-14.3) AG13(7.3,-14.3) AG15(8.3,-14.3) AG17(9.3,-14.3) AG19(10.3,-14.3) AG21(11.3,-14.3) AG23(12.3,-14.3) AG25(13.3,-14.3) AG27(14.3,-14.3) AG29(15.3,-14.3) AG31(16.3,-14.3) AG32(17.3,-14.6) AG34(18.1,-14.6) AG35(18.9,-14.6) AG37(19.7,-14.6) AG38(20.5,-14.6) AJ4(2.1,-15.7) AJ5(2.9,-15.7) AJ7(3.7,-15.7) AJ8(4.5,-15.7) AJ10(5.3,-15.7) AJ11(6.3,-15.3) AJ13(7.3,-15.3) AJ15(8.3,-15.3) AJ17(9.3,-15.3) AJ19(10.3,-15.3) AJ21(11.3,-15.3) AJ23(12.3,-15.3) AJ25(13.3,-15.3) AJ27(14.3,-15.3) AJ29(15.3,-15.3) AJ31(16.3,-15.3) AJ32(17.3,-15.7) AJ34(18.1,-15.7) AJ35(18.9,-15.7) AJ37(19.7,-15.7) AJ38(20.5,-15.7) AL4(2.1,-16.8) AL5(2.9,-16.8) AL7(3.7,-16.8) AL8(4.5,-16.8) AL10(5.3,-16.8) AL11(6.3,-16.3) AL13(7.3,-16.3) AL15(8.3,-16.3) AL17(9.3,-16.3) AL19(10.3,-16.3) AL21(11.3,-16.3) AL23(12.3,-16.3) AL25(13.3,-16.3) AL27(14.3,-16.3) AL29(15.3,-16.3) AL31(16.3,-16.3) AL32(17.3,-16.8) AL34(18.1,-16.8) AL35(18.9,-16.8) AL37(19.7,-16.8) AL38(20.5,-16.8) AM11(5.8,-17.3) AM13(6.9,-17.3) AM15(8,-17.3) AM17(9.1,-17.3) AM19(10.2,-17.3) AM21(11.3,-17.3) AM23(12.4,-17.3) AM25(13.5,-17.3) AM27(14.6,-17.3) AM29(15.7,-17.3) AM31(16.8,-17.3) AN4(2.1,-17.9) AN5(2.9,-17.9) AN7(3.7,-17.9) AN8(4.5,-17.9) AN34(18.1,-17.9) AN35(18.9,-17.9) AN37(19.7,-17.9) AN38(20.5,-17.9) AP11(5.8,-18.1) AP13(6.9,-18.1) AP15(8,-18.1) AP17(9.1,-18.1) AP19(10.2,-18.1) AP21(11.3,-18.1) AP23(12.4,-18.1) AP25(13.5,-18.1) AP27(14.6,-18.1) AP29(15.7,-18.1) AP31(16.8,-18.1) AR4(2.1,-19) AR5(2.9,-19) AR7(3.7,-19) AR11(5.8,-18.9) AR13(6.9,-18.9) AR15(8,-18.9) AR17(9.1,-18.9) AR19(10.2,-18.9) AR21(11.3,-18.9) AR23(12.4,-18.9) AR25(13.5,-18.9) AR27(14.6,-18.9) AR29(15.7,-18.9) AR31(16.8,-18.9) AR35(18.9,-19) AR37(19.7,-19) AR38(20.5,-19) AU4(2.1,-20.1) AU7(3.6,-19.7) AU9(4.7,-19.7) AU11(5.8,-19.7) AU13(6.9,-19.7) AU15(8,-19.7) AU17(9.1,-19.7) AU19(10.2,-19.7) AU21(11.3,-19.7) AU23(12.4,-19.7) AU25(13.5,-19.7) AU27(14.6,-19.7) AU29(15.7,-19.7) AU31(16.8,-19.7) AU33(17.9,-19.7) AU35(19,-19.7) AU38(20.5,-20.1) AV7(3.6,-20.5) AV9(4.7,-20.5) AV11(5.8,-20.5) AV13(6.9,-20.5) AV15(8,-20.5) AV17(9.1,-20.5) AV19(10.2,-20.5) AV21(11.3,-20.5) AV23(12.4,-20.5) AV25(13.5,-20.5) AV27(14.6,-20.5) AV29(15.7,-20.5) AV31(16.8,-20.5) AV33(17.9,-20.5) AV35(19,-20.5) AW1(0,-21.25) AW41(22.6,-21.25) AY1(0,-22) AY2(0.7,-21.9) AY40(21.9,-21.9) AY41(22.6,-22) B1(0,-0.6) B2(0.7,-0.7) B40(21.9,-0.7) B41(22.6,-0.6) BA2(0.6,-22.6) BA3(1.35,-22.6) BA39(21.25,-22.6) BA40(22,-22.6) C1(0,-1.35) C41(22.6,-1.35) D7(3.6,-2.1) D9(4.7,-2.1) D11(5.8,-2.1) D13(6.9,-2.1) D15(8,-2.1) D17(9.1,-2.1) D19(10.2,-2.1) D21(11.3,-2.1) D23(12.4,-2.1) D25(13.5,-2.1) D27(14.6,-2.1) D29(15.7,-2.1) D31(16.8,-2.1) D33(17.9,-2.1) D35(19,-2.1) E4(2.1,-2.5) E7(3.6,-2.9) E9(4.7,-2.9) E11(5.8,-2.9) E13(6.9,-2.9) E15(8,-2.9) E17(9.1,-2.9) E19(10.2,-2.9) E21(11.3,-2.9) E23(12.4,-2.9) E25(13.5,-2.9) E27(14.6,-2.9) E29(15.7,-2.9) E31(16.8,-2.9) E33(17.9,-2.9) E35(19,-2.9) E38(20.5,-2.5) G4(2.1,-3.6) G5(2.9,-3.6) G7(3.7,-3.6) G11(5.8,-3.7) G13(6.9,-3.7) G15(8,-3.7) G17(9.1,-3.7) G19(10.2,-3.7) G21(11.3,-3.7) G23(12.4,-3.7) G25(13.5,-3.7) G27(14.6,-3.7) G29(15.7,-3.7) G31(16.8,-3.7) G35(18.9,-3.6) G37(19.7,-3.6) G38(20.5,-3.6) H11(5.8,-4.5) H13(6.9,-4.5) H15(8,-4.5) H17(9.1,-4.5) H19(10.2,-4.5) H21(11.3,-4.5) H23(12.4,-4.5) H25(13.5,-4.5) H27(14.6,-4.5) H29(15.7,-4.5) H31(16.8,-4.5) J4(2.1,-4.7) J5(2.9,-4.7) J7(3.7,-4.7) J8(4.5,-4.7) J34(18.1,-4.7) J35(18.9,-4.7) J37(19.7,-4.7) J38(20.5,-4.7) K11(5.8,-5.3) K13(6.9,-5.3) K15(8,-5.3) K17(9.1,-5.3) K19(10.2,-5.3) K21(11.3,-5.3) K23(12.4,-5.3) K25(13.5,-5.3) K27(14.6,-5.3) K29(15.7,-5.3) K31(16.8,-5.3) L4(2.1,-5.8) L5(2.9,-5.8) L7(3.7,-5.8) L8(4.5,-5.8) L10(5.3,-5.8) L11(6.3,-6.3) L13(7.3,-6.3) L15(8.3,-6.3) L17(9.3,-6.3) L19(10.3,-6.3) L21(11.3,-6.3) L23(12.3,-6.3) L25(13.3,-6.3) L27(14.3,-6.3) L29(15.3,-6.3) L31(16.3,-6.3) L32(17.3,-5.8) L34(18.1,-5.8) L35(18.9,-5.8) L37(19.7,-5.8) L38(20.5,-5.8) N4(2.1,-6.9) N5(2.9,-6.9) N7(3.7,-6.9) N8(4.5,-6.9) N10(5.3,-6.9) N11(6.3,-7.3) N13(7.3,-7.3) N15(8.3,-7.3) N17(9.3,-7.3) N19(10.3,-7.3) N21(11.3,-7.3) N23(12.3,-7.3) N25(13.3,-7.3) N27(14.3,-7.3) N29(15.3,-7.3) N31(16.3,-7.3) N32(17.3,-6.9) N34(18.1,-6.9) N35(18.9,-6.9) N37(19.7,-6.9) N38(20.5,-6.9) R4(2.1,-8) R5(2.9,-8) R7(3.7,-8) R8(4.5,-8) R10(5.3,-8) R11(6.3,-8.3) R13(7.3,-8.3) R15(8.3,-8.3) R17(9.3,-8.3) R19(10.3,-8.3) R21(11.3,-8.3) R23(12.3,-8.3) R25(13.3,-8.3) R27(14.3,-8.3) R29(15.3,-8.3) R31(16.3,-8.3) R32(17.3,-8) R34(18.1,-8) R35(18.9,-8) R37(19.7,-8) R38(20.5,-8) U4(2.1,-9.1) U5(2.9,-9.1) U7(3.7,-9.1) U8(4.5,-9.1) U10(5.3,-9.1) U11(6.3,-9.3) U13(7.3,-9.3) U15(8.3,-9.3) U17(9.3,-9.3) U19(10.3,-9.3) U21(11.3,-9.3) U23(12.3,-9.3) U25(13.3,-9.3) U27(14.3,-9.3) U29(15.3,-9.3) U31(16.3,-9.3) U32(17.3,-9.1) U34(18.1,-9.1) U35(18.9,-9.1) U37(19.7,-9.1) U38(20.5,-9.1) W4(2.1,-10.2) W5(2.9,-10.2) W7(3.7,-10.2) W8(4.5,-10.2) W10(5.3,-10.2) W11(6.3,-10.3) W13(7.3,-10.3) W15(8.3,-10.3) W17(9.3,-10.3) W19(10.3,-10.3) W21(11.3,-10.3) W23(12.3,-10.3) W25(13.3,-10.3) W27(14.3,-10.3) W29(15.3,-10.3) W31(16.3,-10.3) W32(17.3,-10.2) W34(18.1,-10.2) W35(18.9,-10.2) W37(19.7,-10.2) W38(20.5,-10.2)
  round 0.305 smd: A4(1.95,-0.35) A5(2.5,0) A6(3.05,-0.35) A7(3.6,0) A8(4.15,-0.35) A9(4.7,0) A10(5.25,-0.35) A11(5.8,0) A12(6.35,-0.35) A13(6.9,0) A14(7.45,-0.35) A15(8,0) A16(8.55,-0.35) A17(9.1,0) A18(9.65,-0.35) A19(10.2,0) A20(10.75,-0.35) A21(11.3,0) A22(11.85,-0.35) A23(12.4,0) A24(12.95,-0.35) A25(13.5,0) A26(14.05,-0.35) A27(14.6,0) A28(15.15,-0.35) A29(15.7,0) A30(16.25,-0.35) A31(16.8,0) A32(17.35,-0.35) A33(17.9,0) A34(18.45,-0.35) A35(19,0) A36(19.55,-0.35) A37(20.1,0) A38(20.65,-0.35) AA1(0,-11.3) AA2(0.7,-11.3) AA3(1.4,-11.3) AA39(21.2,-11.3) AA40(21.9,-11.3) AA41(22.6,-11.3) AB1(0.35,-11.85) AB2(1.05,-11.85) AB40(21.55,-11.85) AB41(22.25,-11.85) AC1(0,-12.4) AC2(0.7,-12.4) AC3(1.4,-12.4) AC39(21.2,-12.4) AC40(21.9,-12.4) AC41(22.6,-12.4) AD1(0.35,-12.95) AD2(1.05,-12.95) AD40(21.55,-12.95) AD41(22.25,-12.95) AE1(0,-13.5) AE2(0.7,-13.5) AE3(1.4,-13.5) AE39(21.2,-13.5) AE40(21.9,-13.5) AE41(22.6,-13.5) AF1(0.35,-14.05) AF2(1.05,-14.05) AF40(21.55,-14.05) AF41(22.25,-14.05) AG1(0,-14.6) AG2(0.7,-14.6) AG3(1.4,-14.6) AG39(21.2,-14.6) AG40(21.9,-14.6) AG41(22.6,-14.6) AH1(0.35,-15.15) AH2(1.05,-15.15) AH40(21.55,-15.15) AH41(22.25,-15.15) AJ1(0,-15.7) AJ2(0.7,-15.7) AJ3(1.4,-15.7) AJ39(21.2,-15.7) AJ40(21.9,-15.7) AJ41(22.6,-15.7) AK1(0.35,-16.25) AK2(1.05,-16.25) AK40(21.55,-16.25) AK41(22.25,-16.25) AL1(0,-16.8) AL2(0.7,-16.8) AL3(1.4,-16.8) AL39(21.2,-16.8) AL40(21.9,-16.8) AL41(22.6,-16.8) AM1(0.35,-17.35) AM2(1.05,-17.35) AM40(21.55,-17.35) AM41(22.25,-17.35) AN1(0,-17.9) AN2(0.7,-17.9) AN3(1.4,-17.9) AN39(21.2,-17.9) AN40(21.9,-17.9) AN41(22.6,-17.9) AP1(0.35,-18.45) AP2(1.05,-18.45) AP40(21.55,-18.45) AP41(22.25,-18.45) AR1(0,-19) AR2(0.7,-19) AR3(1.4,-19) AR39(21.2,-19) AR40(21.9,-19) AR41(22.6,-19) AT1(0.35,-19.55) AT2(1.05,-19.55) AT40(21.55,-19.55) AT41(22.25,-19.55) AU1(0,-20.1) AU2(0.7,-20.1) AU3(1.4,-20.1) AU39(21.2,-20.1) AU40(21.9,-20.1) AU41(22.6,-20.1) AV1(0.35,-20.65) AV2(1.05,-20.65) AV40(21.55,-20.65) AV41(22.25,-20.65) AW2(0.7,-21.2) AW3(1.4,-21.2) AW5(2.5,-21.2) AW7(3.6,-21.2) AW9(4.7,-21.2) AW11(5.8,-21.2) AW13(6.9,-21.2) AW15(8,-21.2) AW17(9.1,-21.2) AW19(10.2,-21.2) AW21(11.3,-21.2) AW23(12.4,-21.2) AW25(13.5,-21.2) AW27(14.6,-21.2) AW29(15.7,-21.2) AW31(16.8,-21.2) AW33(17.9,-21.2) AW35(19,-21.2) AW37(20.1,-21.2) AW39(21.2,-21.2) AW40(21.9,-21.2) AY3(1.4,-21.9) AY4(1.95,-21.55) AY5(2.5,-21.9) AY6(3.05,-21.55) AY7(3.6,-21.9) AY8(4.15,-21.55) AY9(4.7,-21.9) AY10(5.25,-21.55) AY11(5.8,-21.9) AY12(6.35,-21.55) AY13(6.9,-21.9) AY14(7.45,-21.55) AY15(8,-21.9) AY16(8.55,-21.55) AY17(9.1,-21.9) AY18(9.65,-21.55) AY19(10.2,-21.9) AY20(10.75,-21.55) AY21(11.3,-21.9) AY22(11.85,-21.55) AY23(12.4,-21.9) AY24(12.95,-21.55) AY25(13.5,-21.9) AY26(14.05,-21.55) AY27(14.6,-21.9) AY28(15.15,-21.55) AY29(15.7,-21.9) AY30(16.25,-21.55) AY31(16.8,-21.9) AY32(17.35,-21.55) AY33(17.9,-21.9) AY34(18.45,-21.55) AY35(19,-21.9) AY36(19.55,-21.55) AY37(20.1,-21.9) AY38(20.65,-21.55) AY39(21.2,-21.9) B3(1.4,-0.7) B4(1.95,-1.05) B5(2.5,-0.7) B6(3.05,-1.05) B7(3.6,-0.7) B8(4.15,-1.05) B9(4.7,-0.7) B10(5.25,-1.05) B11(5.8,-0.7) B12(6.35,-1.05) B13(6.9,-0.7) B14(7.45,-1.05) B15(8,-0.7) B16(8.55,-1.05) B17(9.1,-0.7) B18(9.65,-1.05) B19(10.2,-0.7) B20(10.75,-1.05) B21(11.3,-0.7) B22(11.85,-1.05) B23(12.4,-0.7) B24(12.95,-1.05) B25(13.5,-0.7) B26(14.05,-1.05) B27(14.6,-0.7) B28(15.15,-1.05) B29(15.7,-0.7) B30(16.25,-1.05) B31(16.8,-0.7) B32(17.35,-1.05) B33(17.9,-0.7) B34(18.45,-1.05) B35(19,-0.7) B36(19.55,-1.05) B37(20.1,-0.7) B38(20.65,-1.05) B39(21.2,-0.7) BA4(1.95,-22.25) BA5(2.5,-22.6) BA6(3.05,-22.25) BA7(3.6,-22.6) BA8(4.15,-22.25) BA9(4.7,-22.6) BA10(5.25,-22.25) BA11(5.8,-22.6) BA12(6.35,-22.25) BA13(6.9,-22.6) BA14(7.45,-22.25) BA15(8,-22.6) BA16(8.55,-22.25) BA17(9.1,-22.6) BA18(9.65,-22.25) BA19(10.2,-22.6) BA20(10.75,-22.25) BA21(11.3,-22.6) BA22(11.85,-22.25) BA23(12.4,-22.6) BA24(12.95,-22.25) BA25(13.5,-22.6) BA26(14.05,-22.25) BA27(14.6,-22.6) BA28(15.15,-22.25) BA29(15.7,-22.6) BA30(16.25,-22.25) BA31(16.8,-22.6) BA32(17.35,-22.25) BA33(17.9,-22.6) BA34(18.45,-22.25) BA35(19,-22.6) BA36(19.55,-22.25) BA37(20.1,-22.6) BA38(20.65,-22.25) C2(0.7,-1.4) C3(1.4,-1.4) C5(2.5,-1.4) C7(3.6,-1.4) C9(4.7,-1.4) C11(5.8,-1.4) C13(6.9,-1.4) C15(8,-1.4) C17(9.1,-1.4) C19(10.2,-1.4) C21(11.3,-1.4) C23(12.4,-1.4) C25(13.5,-1.4) C27(14.6,-1.4) C29(15.7,-1.4) C31(16.8,-1.4) C33(17.9,-1.4) C35(19,-1.4) C37(20.1,-1.4) C39(21.2,-1.4) C40(21.9,-1.4) D1(0.35,-1.95) D2(1.05,-1.95) D40(21.55,-1.95) D41(22.25,-1.95) E1(0,-2.5) E2(0.7,-2.5) E3(1.4,-2.5) E39(21.2,-2.5) E40(21.9,-2.5) E41(22.6,-2.5) F1(0.35,-3.05) F2(1.05,-3.05) F40(21.55,-3.05) F41(22.25,-3.05) G1(0,-3.6) G2(0.7,-3.6) G3(1.4,-3.6) G39(21.2,-3.6) G40(21.9,-3.6) G41(22.6,-3.6) H1(0.35,-4.15) H2(1.05,-4.15) H40(21.55,-4.15) H41(22.25,-4.15) J1(0,-4.7) J2(0.7,-4.7) J3(1.4,-4.7) J39(21.2,-4.7) J40(21.9,-4.7) J41(22.6,-4.7) K1(0.35,-5.25) K2(1.05,-5.25) K40(21.55,-5.25) K41(22.25,-5.25) L1(0,-5.8) L2(0.7,-5.8) L3(1.4,-5.8) L39(21.2,-5.8) L40(21.9,-5.8) L41(22.6,-5.8) M1(0.35,-6.35) M2(1.05,-6.35) M40(21.55,-6.35) M41(22.25,-6.35) N1(0,-6.9) N2(0.7,-6.9) N3(1.4,-6.9) N39(21.2,-6.9) N40(21.9,-6.9) N41(22.6,-6.9) P1(0.35,-7.45) P2(1.05,-7.45) P40(21.55,-7.45) P41(22.25,-7.45) R1(0,-8) R2(0.7,-8) R3(1.4,-8) R39(21.2,-8) R40(21.9,-8) R41(22.6,-8) T1(0.35,-8.55) T2(1.05,-8.55) T40(21.55,-8.55) T41(22.25,-8.55) U1(0,-9.1) U2(0.7,-9.1) U3(1.4,-9.1) U39(21.2,-9.1) U40(21.9,-9.1) U41(22.6,-9.1) V1(0.35,-9.65) V2(1.05,-9.65) V40(21.55,-9.65) V41(22.25,-9.65) W1(0,-10.2) W2(0.7,-10.2) W3(1.4,-10.2) W39(21.2,-10.2) W40(21.9,-10.2) W41(22.6,-10.2) Y1(0.35,-10.75) Y2(1.05,-10.75) Y40(21.55,-10.75) Y41(22.25,-10.75)
2N7002BKW_SOT323-3
  oval 0.61x0.559 smd: 1(0,0) 2(-0.65,-1.85) 3(0.65,-1.85)
2N7002DW-T-R7_SOT363-6
  oval 0.381x1.397 smd: 1(0,0) 2(0.65,0) 3(1.3,0) 4(1.3,1.725) 5(0.65,1.725) 6(0,1.725)
2N7002K_SOT23-3
  oval 1.016x1.524 smd: 1(0,0) 2(0.965,2.083) 3(-0.965,2.083)
2N7002KDWH_SOT363-6
  oval 0.356x0.889 smd: 1(0,0) 2(0.65,0) 3(1.3,0) 4(1.3,1.6) 5(0.65,1.6) 6(0,1.6)
2N7002KW_SOT323-3
  oval 0.66x0.864 smd: 1(0,0) 2(0.65,1.85) 3(-0.65,1.85)
5A_Z150_1210_2P
  rect 0.991x2.997 smd: 1(0,0) 2(2.7,0)
216-0842024-A11-MAR_FCBGA_631P
  round 0.406 smd: A3(0.8,0) A30(20.8,0) A32(21.6,0) AB7(3.2,-15) AB8(4,-15) AB9(4.8,-15) AB10(5.6,-15) AB23(16,-15) AB24(16.8,-15) AB25(17.6,-15) AB26(18.4,-15) AC11(6.6,-16) AC13(7.8,-16) AC14(9,-16) AC16(10.2,-16) AC17(11.4,-16) AC19(12.6,-16) AC20(13.8,-16) AC22(15,-16) AD11(6.6,-16.8) AD13(7.8,-16.8) AD14(9,-16.8) AD16(10.2,-16.8) AD17(11.4,-16.8) AD19(12.6,-16.8) AD20(13.8,-16.8) AD22(15,-16.8) AE11(6.6,-17.6) AE13(7.8,-17.6) AE14(9,-17.6) AE16(10.2,-17.6) AE17(11.4,-17.6) AE19(12.6,-17.6) AE20(13.8,-17.6) AE22(15,-17.6) AF11(6.6,-18.4) AF13(7.8,-18.4) AF14(9,-18.4) AF16(10.2,-18.4) AF17(11.4,-18.4) AF19(12.6,-18.4) AF20(13.8,-18.4) AF22(15,-18.4) AK1(0,-20.8) AK3(0.8,-20.8) AK30(20.8,-20.8) AK32(21.6,-20.8) AM1(0,-21.6) AM3(0.8,-21.6) AM30(20.8,-21.6) AM32(21.6,-21.6) C1(0,-0.8) C3(0.8,-0.8) C30(20.8,-0.8) C32(21.6,-0.8) G11(6.6,-3.2) G13(7.8,-3.2) G14(9,-3.2) G16(10.2,-3.2) G17(11.4,-3.2) G19(12.6,-3.2) G20(13.8,-3.2) G22(15,-3.2) H11(6.6,-4) H13(7.8,-4) H14(9,-4) H16(10.2,-4) H17(11.4,-4) H19(12.6,-4) H20(13.8,-4) H22(15,-4) J11(6.6,-4.8) J13(7.8,-4.8) J14(9,-4.8) J16(10.2,-4.8) J17(11.4,-4.8) J19(12.6,-4.8) J20(13.8,-4.8) J22(15,-4.8) K11(6.6,-5.6) K13(7.8,-5.6) K14(9,-5.6) K16(10.2,-5.6) K17(11.4,-5.6) K19(12.6,-5.6) K20(13.8,-5.6) K22(15,-5.6) L7(3.2,-6.6) L8(4,-6.6) L9(4.8,-6.6) L10(5.6,-6.6) L23(16,-6.6) L24(16.8,-6.6) L25(17.6,-6.6) L26(18.4,-6.6) N7(3.2,-7.8) N8(4,-7.8) N9(4.8,-7.8) N10(5.6,-7.8) N23(16,-7.8) N24(16.8,-7.8) N25(17.6,-7.8) N26(18.4,-7.8) P7(3.2,-9) P8(4,-9) P9(4.8,-9) P10(5.6,-9) P23(16,-9) P24(16.8,-9) P25(17.6,-9) P26(18.4,-9) T7(3.2,-10.2) T8(4,-10.2) T9(4.8,-10.2) T10(5.6,-10.2) T23(16,-10.2) T24(16.8,-10.2) T25(17.6,-10.2) T26(18.4,-10.2) U7(3.2,-11.4) U8(4,-11.4) U9(4.8,-11.4) U10(5.6,-11.4) U23(16,-11.4) U24(16.8,-11.4) U25(17.6,-11.4) U26(18.4,-11.4) W7(3.2,-12.6) W8(4,-12.6) W9(4.8,-12.6) W10(5.6,-12.6) W23(16,-12.6) W24(16.8,-12.6) W25(17.6,-12.6) W26(18.4,-12.6) Y7(3.2,-13.8) Y8(4,-13.8) Y9(4.8,-13.8) Y10(5.6,-13.8) Y23(16,-13.8) Y24(16.8,-13.8) Y25(17.6,-13.8) Y26(18.4,-13.8)
  round 0.305 smd: A5(1.6,0) A7(3.2,0) A9(4.8,0) A11(6.4,0) A13(8,0) A15(9.6,0) A17(11.2,0) A19(12.8,0) A21(14.4,0) A23(16,0) A25(17.6,0) A27(19.2,0) A28(20,0) AA1(0,-14.4) AA3(0.8,-14.4) AA5(1.6,-14.4) AA6(2.4,-14.4) AA27(19.2,-14.4) AA29(20.4,-14.4) AA31(21.2,-14.4) AB2(0.4,-15.2) AB4(1.2,-15.2) AB6(2.4,-15.2) AB27(19.2,-15.2) AB28(20,-15.2) AB30(20.8,-15.2) AB32(21.6,-15.2) AC1(0,-16) AC3(0.8,-16) AC5(1.6,-16) AC6(2.4,-16) AC7(3.2,-16) AC8(4,-16) AC9(4.8,-16) AC10(5.6,-16) AC23(16,-16) AC24(16.8,-16) AC25(17.6,-16) AC26(18.4,-16) AC27(19.2,-16) AC29(20.4,-16) AC31(21.2,-16) AD2(0.4,-16.8) AD4(1.2,-16.8) AD6(2.4,-16.8) AD7(3.2,-16.8) AD8(4,-16.8) AD9(4.8,-16.8) AD10(5.6,-16.8) AD23(16,-16.8) AD24(16.8,-16.8) AD25(17.6,-16.8) AD26(18.4,-16.8) AD27(19.2,-16.8) AD28(20,-16.8) AD30(20.8,-16.8) AD32(21.6,-16.8) AE1(0,-17.6) AE3(0.8,-17.6) AE5(1.6,-17.6) AE6(2.4,-17.6) AE7(3.2,-17.6) AE8(4,-17.6) AE9(4.8,-17.6) AE10(5.6,-17.6) AE23(16,-17.6) AE24(16.8,-17.6) AE25(17.6,-17.6) AE26(18.4,-17.6) AE27(19.2,-17.6) AE29(20.4,-17.6) AE31(21.2,-17.6) AF2(0.4,-18.4) AF4(1.2,-18.4) AF6(2.4,-18.4) AF7(3.2,-18.4) AF8(4,-18.4) AF9(4.8,-18.4) AF10(5.6,-18.4) AF23(16,-18.4) AF24(16.8,-18.4) AF25(17.6,-18.4) AF26(18.4,-18.4) AF27(19.2,-18.4) AF28(20,-18.4) AF30(20.8,-18.4) AF32(21.6,-18.4) AG1(0,-19.2) AG3(0.8,-19.2) AG5(1.6,-19.2) AG6(2.4,-19.2) AG7(3.2,-19.2) AG8(4,-19.2) AG9(4.8,-19.2) AG10(5.6,-19.2) AG11(6.4,-19.2) AG12(7.2,-19.2) AG13(8,-19.2) AG14(8.8,-19.2) AG15(9.6,-19.2) AG16(10.4,-19.2) AG17(11.2,-19.2) AG18(12,-19.2) AG19(12.8,-19.2) AG20(13.6,-19.2) AG21(14.4,-19.2) AG22(15.2,-19.2) AG23(16,-19.2) AG24(16.8,-19.2) AG25(17.6,-19.2) AG26(18.4,-19.2) AG27(19.2,-19.2) AG29(20.4,-19.2) AG31(21.2,-19.2) AH1(0,-20) AH3(0.8,-20) AH5(1.6,-20) AH6(2.4,-20) AH8(4,-20) AH10(5.6,-20) AH12(7.2,-20) AH14(8.8,-20) AH16(10.4,-20) AH18(12,-20) AH20(13.6,-20) AH22(15.2,-20) AH24(16.8,-20) AH26(18.4,-20) AH28(20,-20) AH30(20.8,-20) AH32(21.6,-20) AJ7(3.2,-20.4) AJ9(4.8,-20.4) AJ11(6.4,-20.4) AJ13(8,-20.4) AJ15(9.6,-20.4) AJ17(11.2,-20.4) AJ19(12.8,-20.4) AJ21(14.4,-20.4) AJ23(16,-20.4) AJ25(17.6,-20.4) AJ27(19.2,-20.4) AK5(1.6,-20.8) AK6(2.4,-20.8) AK8(4,-20.8) AK10(5.6,-20.8) AK12(7.2,-20.8) AK14(8.8,-20.8) AK16(10.4,-20.8) AK18(12,-20.8) AK20(13.6,-20.8) AK22(15.2,-20.8) AK24(16.8,-20.8) AK26(18.4,-20.8) AK28(20,-20.8) AL7(3.2,-21.2) AL9(4.8,-21.2) AL11(6.4,-21.2) AL13(8,-21.2) AL15(9.6,-21.2) AL17(11.2,-21.2) AL19(12.8,-21.2) AL21(14.4,-21.2) AL23(16,-21.2) AL25(17.6,-21.2) AL27(19.2,-21.2) AM5(1.6,-21.6) AM6(2.4,-21.6) AM8(4,-21.6) AM10(5.6,-21.6) AM12(7.2,-21.6) AM14(8.8,-21.6) AM16(10.4,-21.6) AM18(12,-21.6) AM20(13.6,-21.6) AM22(15.2,-21.6) AM24(16.8,-21.6) AM26(18.4,-21.6) AM28(20,-21.6) B6(2.4,-0.4) B8(4,-0.4) B10(5.6,-0.4) B12(7.2,-0.4) B14(8.8,-0.4) B16(10.4,-0.4) B18(12,-0.4) B20(13.6,-0.4) B22(15.2,-0.4) B24(16.8,-0.4) B26(18.4,-0.4) C5(1.6,-0.8) C7(3.2,-0.8) C9(4.8,-0.8) C11(6.4,-0.8) C13(8,-0.8) C15(9.6,-0.8) C17(11.2,-0.8) C19(12.8,-0.8) C21(14.4,-0.8) C23(16,-0.8) C25(17.6,-0.8) C27(19.2,-0.8) C28(20,-0.8) D6(2.4,-1.2) D8(4,-1.2) D10(5.6,-1.2) D12(7.2,-1.2) D14(8.8,-1.2) D16(10.4,-1.2) D18(12,-1.2) D20(13.6,-1.2) D22(15.2,-1.2) D24(16.8,-1.2) D26(18.4,-1.2) E1(0,-1.6) E3(0.8,-1.6) E5(1.6,-1.6) E7(3.2,-1.6) E9(4.8,-1.6) E11(6.4,-1.6) E13(8,-1.6) E15(9.6,-1.6) E17(11.2,-1.6) E19(12.8,-1.6) E21(14.4,-1.6) E23(16,-1.6) E25(17.6,-1.6) E27(19.2,-1.6) E28(20,-1.6) E30(20.8,-1.6) E32(21.6,-1.6) F2(0.4,-2.4) F4(1.2,-2.4) F6(2.4,-2.4) F7(3.2,-2.4) F8(4,-2.4) F9(4.8,-2.4) F10(5.6,-2.4) F11(6.4,-2.4) F12(7.2,-2.4) F13(8,-2.4) F14(8.8,-2.4) F15(9.6,-2.4) F16(10.4,-2.4) F17(11.2,-2.4) F18(12,-2.4) F19(12.8,-2.4) F20(13.6,-2.4) F21(14.4,-2.4) F22(15.2,-2.4) F23(16,-2.4) F24(16.8,-2.4) F25(17.6,-2.4) F26(18.4,-2.4) F27(19.2,-2.4) F28(20,-2.4) F30(20.8,-2.4) F32(21.6,-2.4) G1(0,-3.2) G3(0.8,-3.2) G5(1.6,-3.2) G6(2.4,-3.2) G7(3.2,-3.2) G8(4,-3.2) G9(4.8,-3.2) G10(5.6,-3.2) G23(16,-3.2) G24(16.8,-3.2) G25(17.6,-3.2) G26(18.4,-3.2) G27(19.2,-3.2) G29(20.4,-3.2) G31(21.2,-3.2) H2(0.4,-4) H4(1.2,-4) H6(2.4,-4) H7(3.2,-4) H8(4,-4) H9(4.8,-4) H10(5.6,-4) H23(16,-4) H24(16.8,-4) H25(17.6,-4) H26(18.4,-4) H27(19.2,-4) H28(20,-4) H30(20.8,-4) H32(21.6,-4) J1(0,-4.8) J3(0.8,-4.8) J5(1.6,-4.8) J6(2.4,-4.8) J7(3.2,-4.8) J8(4,-4.8) J9(4.8,-4.8) J10(5.6,-4.8) J23(16,-4.8) J24(16.8,-4.8) J25(17.6,-4.8) J26(18.4,-4.8) J27(19.2,-4.8) J29(20.4,-4.8) J31(21.2,-4.8) K2(0.4,-5.6) K4(1.2,-5.6) K6(2.4,-5.6) K7(3.2,-5.6) K8(4,-5.6) K9(4.8,-5.6) K10(5.6,-5.6) K23(16,-5.6) K24(16.8,-5.6) K25(17.6,-5.6) K26(18.4,-5.6) K27(19.2,-5.6) K28(20,-5.6) K30(20.8,-5.6) K32(21.6,-5.6) L1(0,-6.4) L3(0.8,-6.4) L5(1.6,-6.4) L6(2.4,-6.4) L27(19.2,-6.4) L29(20.4,-6.4) L31(21.2,-6.4) M2(0.4,-7.2) M4(1.2,-7.2) M6(2.4,-7.2) M27(19.2,-7.2) M28(20,-7.2) M30(20.8,-7.2) M32(21.6,-7.2) N1(0,-8) N3(0.8,-8) N5(1.6,-8) N6(2.4,-8) N27(19.2,-8) N29(20.4,-8) N31(21.2,-8) P2(0.4,-8.8) P4(1.2,-8.8) P6(2.4,-8.8) P27(19.2,-8.8) P28(20,-8.8) P30(20.8,-8.8) P32(21.6,-8.8) R1(0,-9.6) R3(0.8,-9.6) R5(1.6,-9.6) R6(2.4,-9.6) R27(19.2,-9.6) R29(20.4,-9.6) R31(21.2,-9.6) T2(0.4,-10.4) T4(1.2,-10.4) T6(2.4,-10.4) T27(19.2,-10.4) T28(20,-10.4) T30(20.8,-10.4) T32(21.6,-10.4) U1(0,-11.2) U3(0.8,-11.2) U5(1.6,-11.2) U6(2.4,-11.2) U27(19.2,-11.2) U29(20.4,-11.2) U31(21.2,-11.2) V2(0.4,-12) V4(1.2,-12) V6(2.4,-12) V27(19.2,-12) V28(20,-12) V30(20.8,-12) V32(21.6,-12) W1(0,-12.8) W3(0.8,-12.8) W5(1.6,-12.8) W6(2.4,-12.8) W27(19.2,-12.8) W29(20.4,-12.8) W31(21.2,-12.8) Y2(0.4,-13.6) Y4(1.2,-13.6) Y6(2.4,-13.6) Y27(19.2,-13.6) Y28(20,-13.6) Y30(20.8,-13.6) Y32(21.6,-13.6)
  round 0.508 smd: AA11(6.4,-14.2) AA12(7.4,-14.2) AA13(8.4,-14.2) AA15(9.4,-14.2) AA16(10.4,-14.2) AA17(11.2,-14.2) AA18(12.2,-14.2) AA20(13.2,-14.2) AA21(14.2,-14.2) AA22(15.2,-14.2) AB11(6.4,-15.2) AB12(7.4,-15.2) AB13(8.4,-15.2) AB15(9.4,-15.2) AB16(10.4,-15.2) AB17(11.2,-15.2) AB18(12.2,-15.2) AB20(13.2,-15.2) AB21(14.2,-15.2) AB22(15.2,-15.2) L11(6.4,-6.4) L12(7.4,-6.4) L13(8.4,-6.4) L15(9.4,-6.4) L16(10.4,-6.4) L17(11.2,-6.4) L18(12.2,-6.4) L20(13.2,-6.4) L21(14.2,-6.4) L22(15.2,-6.4) M11(6.4,-7.4) M12(7.4,-7.4) M13(8.4,-7.4) M15(9.4,-7.4) M16(10.4,-7.4) M17(11.2,-7.4) M18(12.2,-7.4) M20(13.2,-7.4) M21(14.2,-7.4) M22(15.2,-7.4) N11(6.4,-8.4) N12(7.4,-8.4) N13(8.4,-8.4) N15(9.4,-8.4) N16(10.4,-8.4) N17(11.2,-8.4) N18(12.2,-8.4) N20(13.2,-8.4) N21(14.2,-8.4) N22(15.2,-8.4) R11(6.4,-9.4) R12(7.4,-9.4) R13(8.4,-9.4) R15(9.4,-9.4) R16(10.4,-9.4) R17(11.2,-9.4) R18(12.2,-9.4) R20(13.2,-9.4) R21(14.2,-9.4) R22(15.2,-9.4) T11(6.4,-10.4) T12(7.4,-10.4) T13(8.4,-10.4) T15(9.4,-10.4) T16(10.4,-10.4) T17(11.2,-10.4) T18(12.2,-10.4) T20(13.2,-10.4) T21(14.2,-10.4) T22(15.2,-10.4) U11(6.4,-11.2) U12(7.4,-11.2) U13(8.4,-11.2) U15(9.4,-11.2) U16(10.4,-11.2) U17(11.2,-11.2) U18(12.2,-11.2) U20(13.2,-11.2) U21(14.2,-11.2) U22(15.2,-11.2) V11(6.4,-12.2) V12(7.4,-12.2) V13(8.4,-12.2) V15(9.4,-12.2) V16(10.4,-12.2) V17(11.2,-12.2) V18(12.2,-12.2) V20(13.2,-12.2) V21(14.2,-12.2) V22(15.2,-12.2) Y11(6.4,-13.2) Y12(7.4,-13.2) Y13(8.4,-13.2) Y15(9.4,-13.2) Y16(10.4,-13.2) Y17(11.2,-13.2) Y18(12.2,-13.2) Y20(13.2,-13.2) Y21(14.2,-13.2) Y22(15.2,-13.2)
